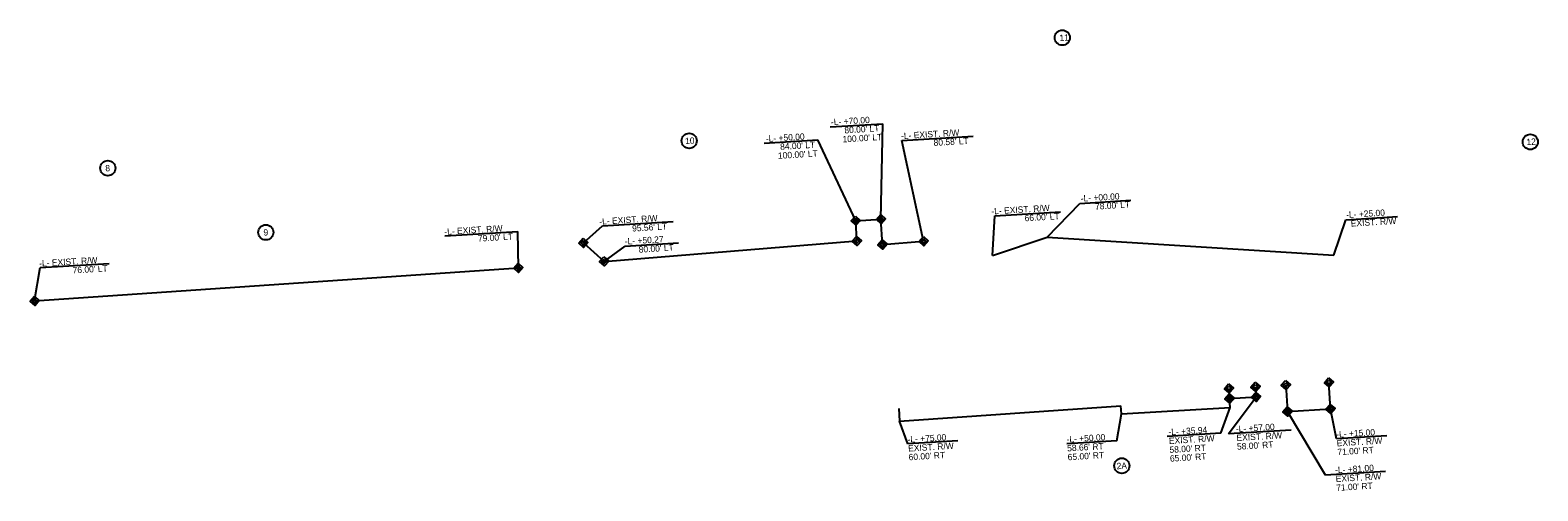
# Model space of a CAD drawing. Extents: x 2111158 to 2113189, y 670264 to 670757.
# Drawn here: x 2111999 to 2113189, y 670393 to 670757 of the extents above; entities that cross this region are included whole.
import ezdxf

# ---------------------------------------------------------------- set-up
doc = ezdxf.new("R2010")
doc.units = 0
for name, color, linetype in [('Exist Guardrail', 7, 'Continuous'), ('Exist Guardrail Text', 7, 'Continuous'), ('Exist Other Culture Anchor (Guy Wire) CELL', 7, 'Continuous'), ('Exist Other Culture Area Outline', 7, 'Continuous'), ('Exist Other Culture Area Outline Leader', 7, 'Continuous'), ('Exist Other Culture Fence Line Text', 7, 'Continuous'), ('Exist Roads Soil', 7, 'Continuous'), ('Exist Structure Minor Footbridge', 7, 'Continuous'), ('Exist Utilities TV Hand Hole CELL', 7, 'Continuous'), ('Exist Utilities TV UG Cable SUE LOS B Cogo Number', 7, 'Continuous'), ('Exist Vegetation Woods Line', 7, 'Continuous'), ('Exist Vegetation Woods Line Text', 7, 'Continuous')]:
    doc.layers.add(name, color=color, linetype=linetype)

msp = doc.modelspace()

# ---------------------------------------------------------------- linework, layer by layer
at = {"layer": 'Exist Guardrail'}
for p, q in [((2112813.8, 670750.7), (2112813.8, 670750.7)), ((2112519.4, 670669.3), (2112519.4, 670669.3)), ((2113183.1, 670668.4), (2113183.1, 670668.4)), ((2112060.6, 670647.7), (2112060.6, 670647.7)), ((2112185.3, 670597), (2112185.3, 670597)), ((2112860.8, 670412.7), (2112860.8, 670412.7))]:
    msp.add_line(p, q, dxfattribs=at)
for centre in [(2112813.8, 670750.7), (2112519.4, 670669.3), (2113183.1, 670668.4), (2112060.6, 670647.7), (2112185.3, 670597), (2112860.8, 670412.7)]:
    msp.add_circle(centre, 6, dxfattribs=at)
at = {"layer": 'Exist Guardrail Text'}
msp.add_line((2112002.9, 670542.9), (2112384.6, 670569), dxfattribs=at)
at = {"layer": 'Exist Other Culture Area Outline'}
for p, q in [((2112684.8, 670458), (2112685.4, 670448)), ((2112685.4, 670448), (2112860, 670459.9)), ((2112860.4, 670453.6), (2112860, 670459.9)), ((2112860.4, 670453.6), (2112946.2, 670458.8)), ((2112946.2, 670458.8), (2112945.7, 670465.8))]:
    msp.add_line(p, q, dxfattribs=at)
at = {"layer": 'Exist Other Culture Area Outline Leader'}
for p, q in [((2112758.7, 670578.6), (2112801.8, 670593.3)), ((2112801.8, 670593.3), (2113028.1, 670579))]:
    msp.add_line(p, q, dxfattribs=at)
at = {"layer": 'Exist Other Culture Fence Line Text'}
for p, q in [((2112671.9, 670587.4), (2112670.7, 670607.4)), ((2112452.3, 670574.1), (2112651.7, 670590.2)), ((2112671.9, 670587.4), (2112704.4, 670590)), ((2112945.2, 670473.8), (2112945.7, 670465.8)), ((2112945.7, 670465.8), (2112966.8, 670467.1)), ((2112966.3, 670475), (2112966.8, 670467.1))]:
    msp.add_line(p, q, dxfattribs=at)
msp.add_lwpolyline([(2112651.7, 670590.2), (2112650.8, 670606.2), (2112670.7, 670607.4)], dxfattribs=at)
at = {"layer": 'Exist Roads Soil'}
for p, q in [((2112827.7, 670619.9), (2112867.9, 670622.4)), ((2112758.7, 670578.6), (2112760.6, 670610)), ((2112760.6, 670610), (2112812.4, 670613.1)), ((2112801.8, 670593.3), (2112827.7, 670619.9)), ((2113037.6, 670607), (2113078.4, 670609.5)), ((2113028.1, 670579), (2113037.6, 670607))]:
    msp.add_line(p, q, dxfattribs=at)
at = {"layer": 'Exist Structure Minor Footbridge'}
for p, q in [((2112630.7, 670680.3), (2112672.3, 670682.8)), ((2112670.7, 670607.4), (2112672.3, 670682.8)), ((2112578.6, 670667.4), (2112620.8, 670670)), ((2112650.8, 670606.2), (2112620.8, 670670)), ((2112687.2, 670669.6), (2112743.4, 670673)), ((2112704.4, 670590), (2112687.2, 670669.6)), ((2112435.9, 670588.7), (2112451.1, 670602.2)), ((2112451.1, 670602.2), (2112506.8, 670605.6)), ((2112650.8, 670606.2), (2112650.8, 670606.2)), ((2112670.7, 670607.4), (2112670.7, 670607.4)), ((2112435.9, 670588.7), (2112435.9, 670588.7)), ((2112452.3, 670574.1), (2112468.9, 670586.2)), ((2112468.9, 670586.2), (2112510.9, 670588.7)), ((2112651.7, 670590.2), (2112651.7, 670590.2)), ((2112671.9, 670587.4), (2112671.9, 670587.4)), ((2112704.4, 670590), (2112704.4, 670590)), ((2112452.3, 670574.1), (2112452.3, 670574.1)), ((2112384.6, 670569), (2112384.6, 670569)), ((2112002.9, 670542.9), (2112002.9, 670542.9)), ((2113024.2, 670478.5), (2113024.2, 670478.5)), ((2112945.2, 670473.8), (2112945.2, 670473.8)), ((2112966.3, 670475), (2112966.3, 670475)), ((2112966.8, 670467.1), (2112966.8, 670467.1)), ((2112990.2, 670476.5), (2112990.2, 670476.5)), ((2112945.7, 670465.8), (2112945.7, 670465.8)), ((2113021.5, 670405.3), (2112991.5, 670455.5)), ((2112991.5, 670455.5), (2112991.5, 670455.5)), ((2113030.2, 670433.9), (2113025.4, 670457.6)), ((2113025.4, 670457.6), (2113025.4, 670457.6)), ((2113069.8, 670436.3), (2113030.2, 670433.9)), ((2113068.9, 670408.2), (2113021.5, 670405.3))]:
    msp.add_line(p, q, dxfattribs=at)
for points in [[(2112650.5, 670609.8), (2112654.4, 670606.4), (2112651, 670602.6), (2112647.2, 670606)], [(2112670.5, 670611), (2112674.3, 670607.6), (2112670.9, 670603.8), (2112667.1, 670607.2)], [(2112670.6, 670609.2), (2112672.5, 670607.5), (2112670.8, 670605.6), (2112668.9, 670607.3)], [(2112650.6, 670608), (2112652.6, 670606.3), (2112650.9, 670604.4), (2112649, 670606.1)], [(2112435.7, 670592.3), (2112439.5, 670588.9), (2112436.1, 670585.1), (2112432.3, 670588.5)], [(2112435.8, 670590.5), (2112437.7, 670588.8), (2112436, 670586.9), (2112434.1, 670588.6)], [(2112651.5, 670593.8), (2112655.3, 670590.4), (2112651.9, 670586.6), (2112648.1, 670590)], [(2112651.6, 670592), (2112653.5, 670590.3), (2112651.8, 670588.4), (2112649.9, 670590.1)], [(2112671.7, 670591), (2112675.5, 670587.7), (2112672.1, 670583.8), (2112668.3, 670587.2)], [(2112671.8, 670589.2), (2112673.7, 670587.5), (2112672, 670585.6), (2112670.1, 670587.3)], [(2112704.2, 670593.6), (2112708, 670590.2), (2112704.6, 670586.4), (2112700.8, 670589.8)], [(2112704.3, 670591.8), (2112706.2, 670590.1), (2112704.5, 670588.2), (2112702.6, 670589.9)], [(2112452.1, 670577.7), (2112455.9, 670574.3), (2112452.6, 670570.5), (2112448.7, 670573.9)], [(2112452.2, 670575.9), (2112454.1, 670574.2), (2112452.4, 670572.3), (2112450.5, 670574)], [(2112384.4, 670572.6), (2112388.2, 670569.2), (2112384.8, 670565.4), (2112381, 670568.8)], [(2112384.5, 670570.8), (2112386.4, 670569.1), (2112384.7, 670567.2), (2112382.8, 670568.9)], [(2112002.7, 670546.5), (2112006.5, 670543.1), (2112003.2, 670539.3), (2111999.3, 670542.7)], [(2112002.8, 670544.7), (2112004.7, 670543), (2112003, 670541.1), (2112001.1, 670542.8)], [(2112966.1, 670478.6), (2112969.9, 670475.3), (2112966.5, 670471.4), (2112962.7, 670474.8)], [(2112990, 670480.1), (2112993.8, 670476.7), (2112990.4, 670472.9), (2112986.6, 670476.3)], [(2112990.1, 670478.3), (2112992, 670476.6), (2112990.3, 670474.7), (2112988.4, 670476.4)], [(2113023.9, 670482.1), (2113027.8, 670478.8), (2113024.4, 670475), (2113020.6, 670478.3)], [(2113024.1, 670480.3), (2113026, 670478.7), (2113024.3, 670476.8), (2113022.4, 670478.4)], [(2112945, 670477.4), (2112948.8, 670474), (2112945.5, 670470.2), (2112941.7, 670473.5)], [(2112945.5, 670469.4), (2112949.3, 670466), (2112946, 670462.2), (2112942.1, 670465.6)], [(2112945.1, 670475.6), (2112947, 670473.9), (2112945.4, 670472), (2112943.5, 670473.7)], [(2112945.6, 670467.6), (2112947.5, 670465.9), (2112945.8, 670464), (2112943.9, 670465.7)], [(2112966.5, 670470.6), (2112970.3, 670467.3), (2112967, 670463.5), (2112963.2, 670466.8)], [(2112966.2, 670476.8), (2112968.1, 670475.1), (2112966.4, 670473.2), (2112964.5, 670474.9)], [(2112966.6, 670468.9), (2112968.6, 670467.2), (2112966.9, 670465.3), (2112965, 670466.9)], [(2112991.3, 670459.1), (2112995.1, 670455.7), (2112991.7, 670451.9), (2112987.9, 670455.3)], [(2112991.4, 670457.3), (2112993.3, 670455.6), (2112991.6, 670453.7), (2112989.7, 670455.4)], [(2113025.2, 670461.2), (2113029, 670457.8), (2113025.7, 670454), (2113021.8, 670457.4)], [(2113025.3, 670459.4), (2113027.2, 670457.7), (2113025.5, 670455.8), (2113023.6, 670457.5)]]:
    msp.add_lwpolyline(points, close=True, dxfattribs=at)
at = {"layer": 'Exist Utilities TV Hand Hole CELL'}
for p, q in [((2112691.9, 670429.9), (2112685.4, 670448)), ((2112856.9, 670432.4), (2112860.4, 670453.6)), ((2112731.4, 670432.3), (2112691.9, 670429.9)), ((2112856.9, 670432.4), (2112817.4, 670430))]:
    msp.add_line(p, q, dxfattribs=at)
at = {"layer": 'Exist Utilities TV UG Cable SUE LOS B Cogo Number'}
for p, q in [((2112326.6, 670594.3), (2112384.1, 670597.7)), ((2112384.6, 670569), (2112384.1, 670597.7)), ((2112002.9, 670542.9), (2112007.2, 670569.2)), ((2112007.2, 670569.2), (2112061.6, 670572.5))]:
    msp.add_line(p, q, dxfattribs=at)
at = {"layer": 'Exist Vegetation Woods Line'}
for p, q in [((2112435.9, 670588.7), (2112452.3, 670574.1)), ((2112945, 670437.9), (2112966.8, 670467.1)), ((2112938.8, 670438.4), (2112946.2, 670458.8)), ((2112938.8, 670438.4), (2112896.6, 670435.8)), ((2112994.4, 670440.9), (2112945, 670437.9))]:
    msp.add_line(p, q, dxfattribs=at)
at = {"layer": 'Exist Vegetation Woods Line Text'}
for p, q in [((2113025.4, 670457.6), (2113024.2, 670478.5)), ((2112990.2, 670476.5), (2112991.5, 670455.5)), ((2112991.5, 670455.5), (2113025.4, 670457.6))]:
    msp.add_line(p, q, dxfattribs=at)

# ---------------------------------------------------------------- texts
at = {"layer": 'Exist Other Culture Anchor (Guy Wire) CELL'}
for s, p in [('11', (2112811.7, 670748)), ('10', (2112516.3, 670666.6)), ('12', (2113180.2, 670665.8)), ('8', (2112058.8, 670645.1)), ('9', (2112183.6, 670594.4)), ('2A', (2112856.8, 670409.9))]:
    msp.add_text(s, height=5, rotation=3.4682, dxfattribs=at).set_placement(p)
at = {"layer": 'Exist Roads Soil'}
for s, p in [('-L- +00.00', (2112828.5, 670621.2)), ("78.00' LT ", (2112839.8, 670614.9)), ('-L- EXIST. R/W', (2112758, 670611.1)), ("66.00' LT ", (2112784.2, 670605.7)), ('-L- +25.00', (2113037.9, 670608.3)), ('EXIST. R/W', (2113041.6, 670601.5))]:
    msp.add_text(s, height=5, rotation=3.4682, dxfattribs=at).set_placement(p)
at = {"layer": 'Exist Structure Minor Footbridge'}
for s, p in [('-L- +70.00', (2112631.4, 670681.5)), ("80.00' LT", (2112642, 670675.1)), ('-L- +50.00', (2112580, 670668.4)), ("84.00' LT", (2112591.3, 670662.1)), ("100.00' LT", (2112640.5, 670668)), ('-L- EXIST. R/W', (2112686.7, 670670.6)), ("80.58' LT ", (2112712.4, 670665.2)), ("100.00' LT", (2112589.6, 670655)), ('-L- EXIST. R/W', (2112448.6, 670603)), ("95.56' LT ", (2112474.5, 670597.6)), ('-L- +50.27', (2112468.7, 670587.3)), ("80.00' LT", (2112479.7, 670580.9)), ('-L- +15.00', (2113030.1, 670434.9)), ('EXIST. R/W', (2113030.5, 670428)), ("71.00' RT", (2113031, 670421)), ('-L- +81.00', (2113029.2, 670406.8)), ('EXIST. R/W', (2113029.7, 670399.8)), ("71.00' RT", (2113030.1, 670392.8))]:
    msp.add_text(s, height=5, rotation=3.4682, dxfattribs=at).set_placement(p)
at = {"layer": 'Exist Utilities TV Hand Hole CELL'}
for s, p in [('-L- +75.00', (2112691.8, 670430.9)), ('EXIST. R/W', (2112692.3, 670423.9)), ('-L- +50.00', (2112817.3, 670431)), ("58.66' RT", (2112817.8, 670424)), ("60.00' RT", (2112692.7, 670417)), ("65.00' RT ", (2112818.2, 670417)), ("65.00' RT ", (2112898.9, 670415.9))]:
    msp.add_text(s, height=5, rotation=3.4682, dxfattribs=at).set_placement(p)
at = {"layer": 'Exist Utilities TV UG Cable SUE LOS B Cogo Number'}
for s, p in [('-L- EXIST. R/W', (2112326.3, 670595)), ("79.00' LT ", (2112352.8, 670589.6)), ('-L- EXIST. R/W', (2112006.6, 670569.9)), ("76.00' LT ", (2112033, 670564.5))]:
    msp.add_text(s, height=5, rotation=3.4682, dxfattribs=at).set_placement(p)
at = {"layer": 'Exist Vegetation Woods Line'}
for s, p in [('-L- +35.94', (2112897.7, 670436.8)), ('-L- +57.00', (2112950.9, 670439.2)), ('EXIST. R/W', (2112898.1, 670429.8)), ('EXIST. R/W', (2112951.4, 670432.2)), ("58.00' RT ", (2112951.8, 670425.3)), ("58.00' RT ", (2112898.5, 670422.8))]:
    msp.add_text(s, height=5, rotation=3.4682, dxfattribs=at).set_placement(p)

doc.saveas('drawing.dxf')
